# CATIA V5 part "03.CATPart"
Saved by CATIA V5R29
Part number: 03
Bounding box of the stored display mesh (mm): x -24 to 24, y -14.5 to 0, z 0 to 16
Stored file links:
  F:\1-Dersler\2-BAHAR\Bilgisayar Destekli Mühendislik Tasarımı\montaj2 el mengenesi\03.CATPart
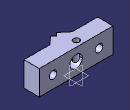
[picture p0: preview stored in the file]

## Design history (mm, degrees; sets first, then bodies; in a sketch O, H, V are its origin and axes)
Body1 (main body)
  Sketch1 on xy-plane, origin (0, 0, 0), H (1, 0, 0), V (0, 1, 0)
    point P1 (-24, 0)
    line L1 (-24, 0) -> (24, 0)
    line L2 (24, 0) -> (24, -10)
    line L3 (24, -10) -> (7.25, -10)
    point P4 (7.25, -10)
    line L4 (7.25, -10) -> (2, -14.5)
    point P5 (2, -14.5)
    line L5 (2, -14.5) -> (0, -12.5)
    point P6 (0, -12.5)
    line L6 (0, -12.5) -> (-2, -14.5)
    point P7 (-2, -14.5)
    line L7 (-2, -14.5) -> (-7.25, -10)
    point P8 (-7.25, -10)
    line L8 (-7.25, -10) -> (-24, -10)
    line L9 (-24, -10) -> (-24, 0)
    length L2 = 10
    length L1 = 48
    distance P7 L1 = 14.5
    distance P8 P4 = 14.5
    distance P7 P5 H = 4
    coincidence: P1 H, P6 V, P8 L3
    horizontal: L1 H, L3 H, L8 H
    vertical: L2 V, L9 V
    symmetry: L5 L6 V, L9 L2 V, P4 P8 V, L4 L7 V
    perpendicularity: L5 L6
  Pad1: profile Sketch1, direction (0, 0, 1), length 16
  Sketch2 on end face of Pad1, origin (-3.707, -3.7668, 16), H (1, 0, 0), V (0, 1, 0)
    point P1 (-0.293, 0)
    reference intersected line E1 (-20.293, -6.2332) -> (-20.293, 3.7668) from face of Pad1 from Sketch1.L9
    distance E1 P1 = 20
  Hole1: placed by Sketch2, at (-4, -3.7668, 16) direction (0, 0, -1), diameter 4, through (limit type 6)
  Sketch3 on face of Pad1 from Sketch1.L1, origin (-0.3386, 0, 9.606), H (1, 0, 0), V (0, 0, -1)
    point P1 (0.3386, 1.606)
    reference intersected line E1 through (0.3386, 0) direction (0, 1) from yz-plane
    reference projected line E2 (24.3386, 9.606) -> (-23.6614, 9.606) from edge [start face of Pad1 | face of Pad1 from Sketch1.L1]
    distance P1 E2 = 8
    coincidence: P1 E1
  Hole2: placed by Sketch3, at (0, 0, 8) direction (0, -1, 0), diameter 8, depth 8.5, V-bottom angle 120
  Sketch4 on face of Pad1 from Sketch1.L8, origin (-17.4186, -10, 8.9518), H (1, 0, 0), V (0, 0, 1)
    point P1 (2.4186, -0.9518)
    reference intersected line E1 through (17.4186, 0) direction (0, 1) from yz-plane
    reference intersected line E2 through (0, -8.9518) direction (-1, 0) from xy-plane
    distance P1 E1 = 15
    distance P1 E2 = 8
  Hole3: placed by Sketch4, at (-15, -10, 8) direction (0, 1, 0), diameter 5, through (limit type 6)
  Mirror1: of Hole3, about yz-plane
